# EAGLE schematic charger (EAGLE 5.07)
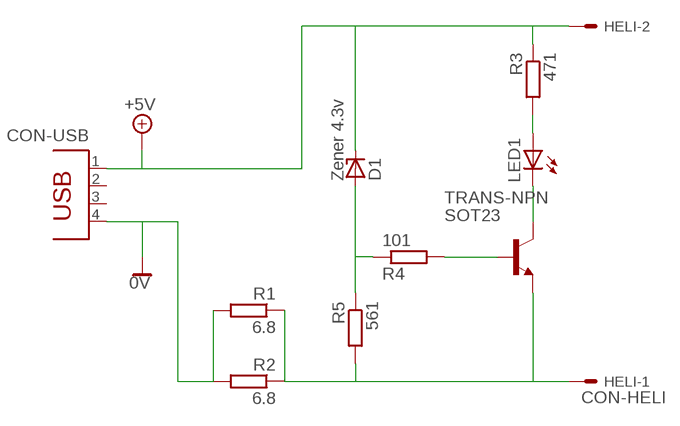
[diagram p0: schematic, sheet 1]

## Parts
CON-USB  PN61729  [PN61729]
D1  Zener 4.3v  1N4728  [DO41Z10]
HELI  CON-HELI  22-23-2021  [22-23-2021]
LED1  LEDLD260  [LD260]
R1  6.8  R-EU_M1406  [M1406]
R2  6.8  R-EU_M1406  [M1406]
R3  471  R-EU_M1406  [M1406]
R4  101  R-EU_M1406  [M1406]
R5  561  R-EU_M1406  [M1406]
TRANS-NPN  SOT23  2N2222  [TO18]

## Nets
0V: CON-USB.4 R1.2 R2.2
+5V: CON-USB.1 D1.C HELI.2 R3.1
N$1: LED1.K(C) TRANS-NPN.3(C)
N$2: LED1.A R3.2
N$3: HELI.1 R1.1 R2.1 R5.2 TRANS-NPN.1(E)
N$4: D1.A R4.1 R5.1
N$5: R4.2 TRANS-NPN.2(B)
Unconnected: CON-USB.2 CON-USB.3

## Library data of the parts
CON-USB = con-berg:PN61729: BERG USB connector
D1 = diode:1N4728: Z DIODE
HELI = con-molex:22-23-2021: .100" (2.54mm) Center Header - 2 Pin
LED1 = led:LED: LED
R1-R5 = resistor:R-EU_: RESISTOR, European symbol
TRANS-NPN = transistor:2N2222: NPN TRANSISTOR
